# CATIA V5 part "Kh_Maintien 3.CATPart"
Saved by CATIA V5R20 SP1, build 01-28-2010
Part number: Maintien 3
Bounding box of the stored display mesh (mm): x -31.991 to 31.991, y -32 to 32, z 0 to 7
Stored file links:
  G:\Khaled_CFAO_2011\SIL\SIL_GR1\tmerino\Khaled\CAD_Thinkmotion\Kh_Maintien 3.CATPart
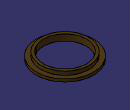
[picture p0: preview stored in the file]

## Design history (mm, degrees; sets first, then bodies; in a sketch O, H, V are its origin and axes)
Body1 (main body)
  Sketch1 on yz-plane, origin (0, 0, 0), H (0, 1, 0), V (0, 0, 1)
    line L1 (24, 7) -> (24, 0)
    line L2 (24, 0) -> (32, 0)
    line L3 (32, 0) -> (32, 3)
    line L4 (32, 3) -> (27, 3)
    line L5 (27, 3) -> (27, 7)
    line L6 (27, 7) -> (24, 7)
    distance V L1 = 24
    distance L1 L5 = 3
    distance L1 L3 = 8
    distance L6 L4 = 4
    distance L4 L2 = 3
    vertical: L1 V, L3 V, L5 V
    horizontal: L2 H, L4 H, L6 H
  Shaft1: profile Sketch1, axis Sketch1.V, angle 360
